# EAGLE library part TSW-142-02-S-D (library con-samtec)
THROUGH-HOLE .025" SQ POST HEADER Source: Samtec TSW.pdf
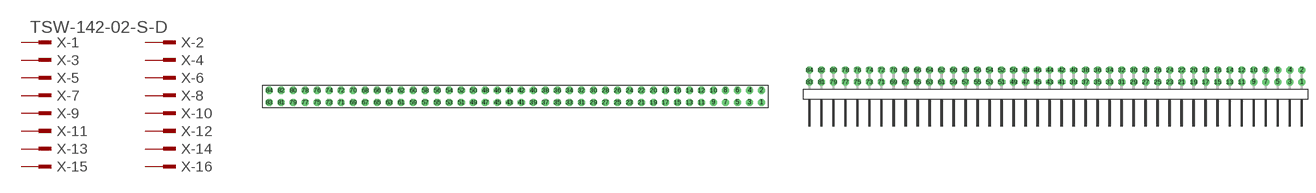
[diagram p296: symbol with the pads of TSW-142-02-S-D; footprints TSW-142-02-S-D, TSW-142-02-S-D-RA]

Designator prefix X; gates -1=MPINV -2=MPIN -3=MPIN -4=MPIN -5=MPIN -6=MPIN -7=MPIN -8=MPIN -9=MPIN -10=MPIN -11=MPIN -12=MPIN -13=MPIN -14=MPIN -15=MPIN -16=MPIN -17=MPIN -18=MPIN -19=MPIN -20=MPIN -21=MPIN -22=MPIN -23=MPIN -24=MPIN -25=MPIN -26=MPIN -27=MPIN -28=MPIN -29=MPIN -30=MPIN -31=MPIN -32=MPIN -33=MPIN -34=MPIN -35=MPIN -36=MPIN -37=MPIN -38=MPIN -39=MPIN -40=MPIN -41=MPIN -42=MPIN -43=MPIN -44=MPIN -45=MPIN -46=MPIN -47=MPIN -48=MPIN -49=MPIN -50=MPIN -51=MPIN -52=MPIN -53=MPIN -54=MPIN -55=MPIN -56=MPIN -57=MPIN -58=MPIN -59=MPIN -60=MPIN -61=MPIN -62=MPIN -63=MPIN -64=MPIN -65=MPIN -66=MPIN -67=MPIN -68=MPIN -69=MPIN -70=MPIN -71=MPIN -72=MPIN -73=MPIN -74=MPIN -75=MPIN -76=MPIN -77=MPIN -78=MPIN -79=MPIN -80=MPIN -81=MPIN -82=MPIN -83=MPIN -84=MPIN

## TSW-142-02-S-D (OC_FARNELL: unknown; OC_NEWARK: unknown)  [TSW-142-02-S-D]
1  -1:1  pas
2  -2:1  pas
3  -3:1  pas
4  -4:1  pas
5  -5:1  pas
6  -6:1  pas
7  -7:1  pas
8  -8:1  pas
9  -9:1  pas
10  -10:1  pas
11  -11:1  pas
12  -12:1  pas
13  -13:1  pas
14  -14:1  pas
15  -15:1  pas
16  -16:1  pas
17  -17:1  pas
18  -18:1  pas
19  -19:1  pas
20  -20:1  pas
21  -21:1  pas
22  -22:1  pas
23  -23:1  pas
24  -24:1  pas
25  -25:1  pas
26  -26:1  pas
27  -27:1  pas
28  -28:1  pas
29  -29:1  pas
30  -30:1  pas
31  -31:1  pas
32  -32:1  pas
33  -33:1  pas
34  -34:1  pas
35  -35:1  pas
36  -36:1  pas
37  -37:1  pas
38  -38:1  pas
39  -39:1  pas
40  -40:1  pas
41  -41:1  pas
42  -42:1  pas
43  -43:1  pas
44  -44:1  pas
45  -45:1  pas
46  -46:1  pas
47  -47:1  pas
48  -48:1  pas
49  -49:1  pas
50  -50:1  pas
51  -51:1  pas
52  -52:1  pas
53  -53:1  pas
54  -54:1  pas
55  -55:1  pas
56  -56:1  pas
57  -57:1  pas
58  -58:1  pas
59  -59:1  pas
60  -60:1  pas
61  -61:1  pas
62  -62:1  pas
63  -63:1  pas
64  -64:1  pas
65  -65:1  pas
66  -66:1  pas
67  -67:1  pas
68  -68:1  pas
69  -69:1  pas
70  -70:1  pas
71  -71:1  pas
72  -72:1  pas
73  -73:1  pas
74  -74:1  pas
75  -75:1  pas
76  -76:1  pas
77  -77:1  pas
78  -78:1  pas
79  -79:1  pas
80  -80:1  pas
81  -81:1  pas
82  -82:1  pas
83  -83:1  pas
84  -84:1  pas

## TSW-142-02-S-D-RA (OC_FARNELL: unknown; OC_NEWARK: unknown)  [TSW-142-02-S-D-RA]
Pads as for TSW-142-02-S-D

## Footprint TSW-142-02-S-D (pad centres in mm)
THROUGH-HOLE .025" SQ POST HEADER Source: Samtec TSW.pdf
drill 1 pad 1.5 octagon: 1 52.07,-1.27; 2 52.07,1.27; 3 49.53,-1.27; 4 49.53,1.27; 5 46.99,-1.27; 6 46.99,1.27; 7 44.45,-1.27; 8 44.45,1.27; 9 41.91,-1.27; 10 41.91,1.27; 11 39.37,-1.27; 12 39.37,1.27; 13 36.83,-1.27; 14 36.83,1.27; 15 34.29,-1.27; 16 34.29,1.27; 17 31.75,-1.27; 18 31.75,1.27; 19 29.21,-1.27; 20 29.21,1.27; 21 26.67,-1.27; 22 26.67,1.27; 23 24.13,-1.27; 24 24.13,1.27; 25 21.59,-1.27; 26 21.59,1.27; 27 19.05,-1.27; 28 19.05,1.27; 29 16.51,-1.27; 30 16.51,1.27; 31 13.97,-1.27; 32 13.97,1.27; 33 11.43,-1.27; 34 11.43,1.27; 35 8.89,-1.27; 36 8.89,1.27; 37 6.35,-1.27; 38 6.35,1.27; 39 3.81,-1.27; 40 3.81,1.27; 41 1.27,-1.27; 42 1.27,1.27; 43 -1.27,-1.27; 44 -1.27,1.27; 45 -3.81,-1.27; 46 -3.81,1.27; 47 -6.35,-1.27; 48 -6.35,1.27; 49 -8.89,-1.27; 50 -8.89,1.27; 51 -11.43,-1.27; 52 -11.43,1.27; 53 -13.97,-1.27; 54 -13.97,1.27; 55 -16.51,-1.27; 56 -16.51,1.27; 57 -19.05,-1.27; 58 -19.05,1.27; 59 -21.59,-1.27; 60 -21.59,1.27; 61 -24.13,-1.27; 62 -24.13,1.27; 63 -26.67,-1.27; 64 -26.67,1.27; 65 -29.21,-1.27; 66 -29.21,1.27; 67 -31.75,-1.27; 68 -31.75,1.27; 69 -34.29,-1.27; 70 -34.29,1.27; 71 -36.83,-1.27; 72 -36.83,1.27; 73 -39.37,-1.27; 74 -39.37,1.27; 75 -41.91,-1.27; 76 -41.91,1.27; 77 -44.45,-1.27; 78 -44.45,1.27; 79 -46.99,-1.27; 80 -46.99,1.27; 81 -49.53,-1.27; 82 -49.53,1.27; 83 -52.07,-1.27; 84 -52.07,1.27

## Footprint TSW-142-02-S-D-RA (pad centres in mm)
THROUGH-HOLE .025" SQ POST HEADER Source: Samtec TSW.pdf
drill 1 pad 1.5 octagon: 1 52.07,1.524; 2 52.07,4.064; 3 49.53,1.524; 4 49.53,4.064; 5 46.99,1.524; 6 46.99,4.064; 7 44.45,1.524; 8 44.45,4.064; 9 41.91,1.524; 10 41.91,4.064; 11 39.37,1.524; 12 39.37,4.064; 13 36.83,1.524; 14 36.83,4.064; 15 34.29,1.524; 16 34.29,4.064; 17 31.75,1.524; 18 31.75,4.064; 19 29.21,1.524; 20 29.21,4.064; 21 26.67,1.524; 22 26.67,4.064; 23 24.13,1.524; 24 24.13,4.064; 25 21.59,1.524; 26 21.59,4.064; 27 19.05,1.524; 28 19.05,4.064; 29 16.51,1.524; 30 16.51,4.064; 31 13.97,1.524; 32 13.97,4.064; 33 11.43,1.524; 34 11.43,4.064; 35 8.89,1.524; 36 8.89,4.064; 37 6.35,1.524; 38 6.35,4.064; 39 3.81,1.524; 40 3.81,4.064; 41 1.27,1.524; 42 1.27,4.064; 43 -1.27,1.524; 44 -1.27,4.064; 45 -3.81,1.524; 46 -3.81,4.064; 47 -6.35,1.524; 48 -6.35,4.064; 49 -8.89,1.524; 50 -8.89,4.064; 51 -11.43,1.524; 52 -11.43,4.064; 53 -13.97,1.524; 54 -13.97,4.064; 55 -16.51,1.524; 56 -16.51,4.064; 57 -19.05,1.524; 58 -19.05,4.064; 59 -21.59,1.524; 60 -21.59,4.064; 61 -24.13,1.524; 62 -24.13,4.064; 63 -26.67,1.524; 64 -26.67,4.064; 65 -29.21,1.524; 66 -29.21,4.064; 67 -31.75,1.524; 68 -31.75,4.064; 69 -34.29,1.524; 70 -34.29,4.064; 71 -36.83,1.524; 72 -36.83,4.064; 73 -39.37,1.524; 74 -39.37,4.064; 75 -41.91,1.524; 76 -41.91,4.064; 77 -44.45,1.524; 78 -44.45,4.064; 79 -46.99,1.524; 80 -46.99,4.064; 81 -49.53,1.524; 82 -49.53,4.064; 83 -52.07,1.524; 84 -52.07,4.064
